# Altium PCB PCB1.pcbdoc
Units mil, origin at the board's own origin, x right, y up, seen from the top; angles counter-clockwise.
Board outline 2074.8 x 2271.65 mil, 2 copper layers (Top Layer, Bottom Layer); 7 components, 8 nets, 23 pads, 0 vias.
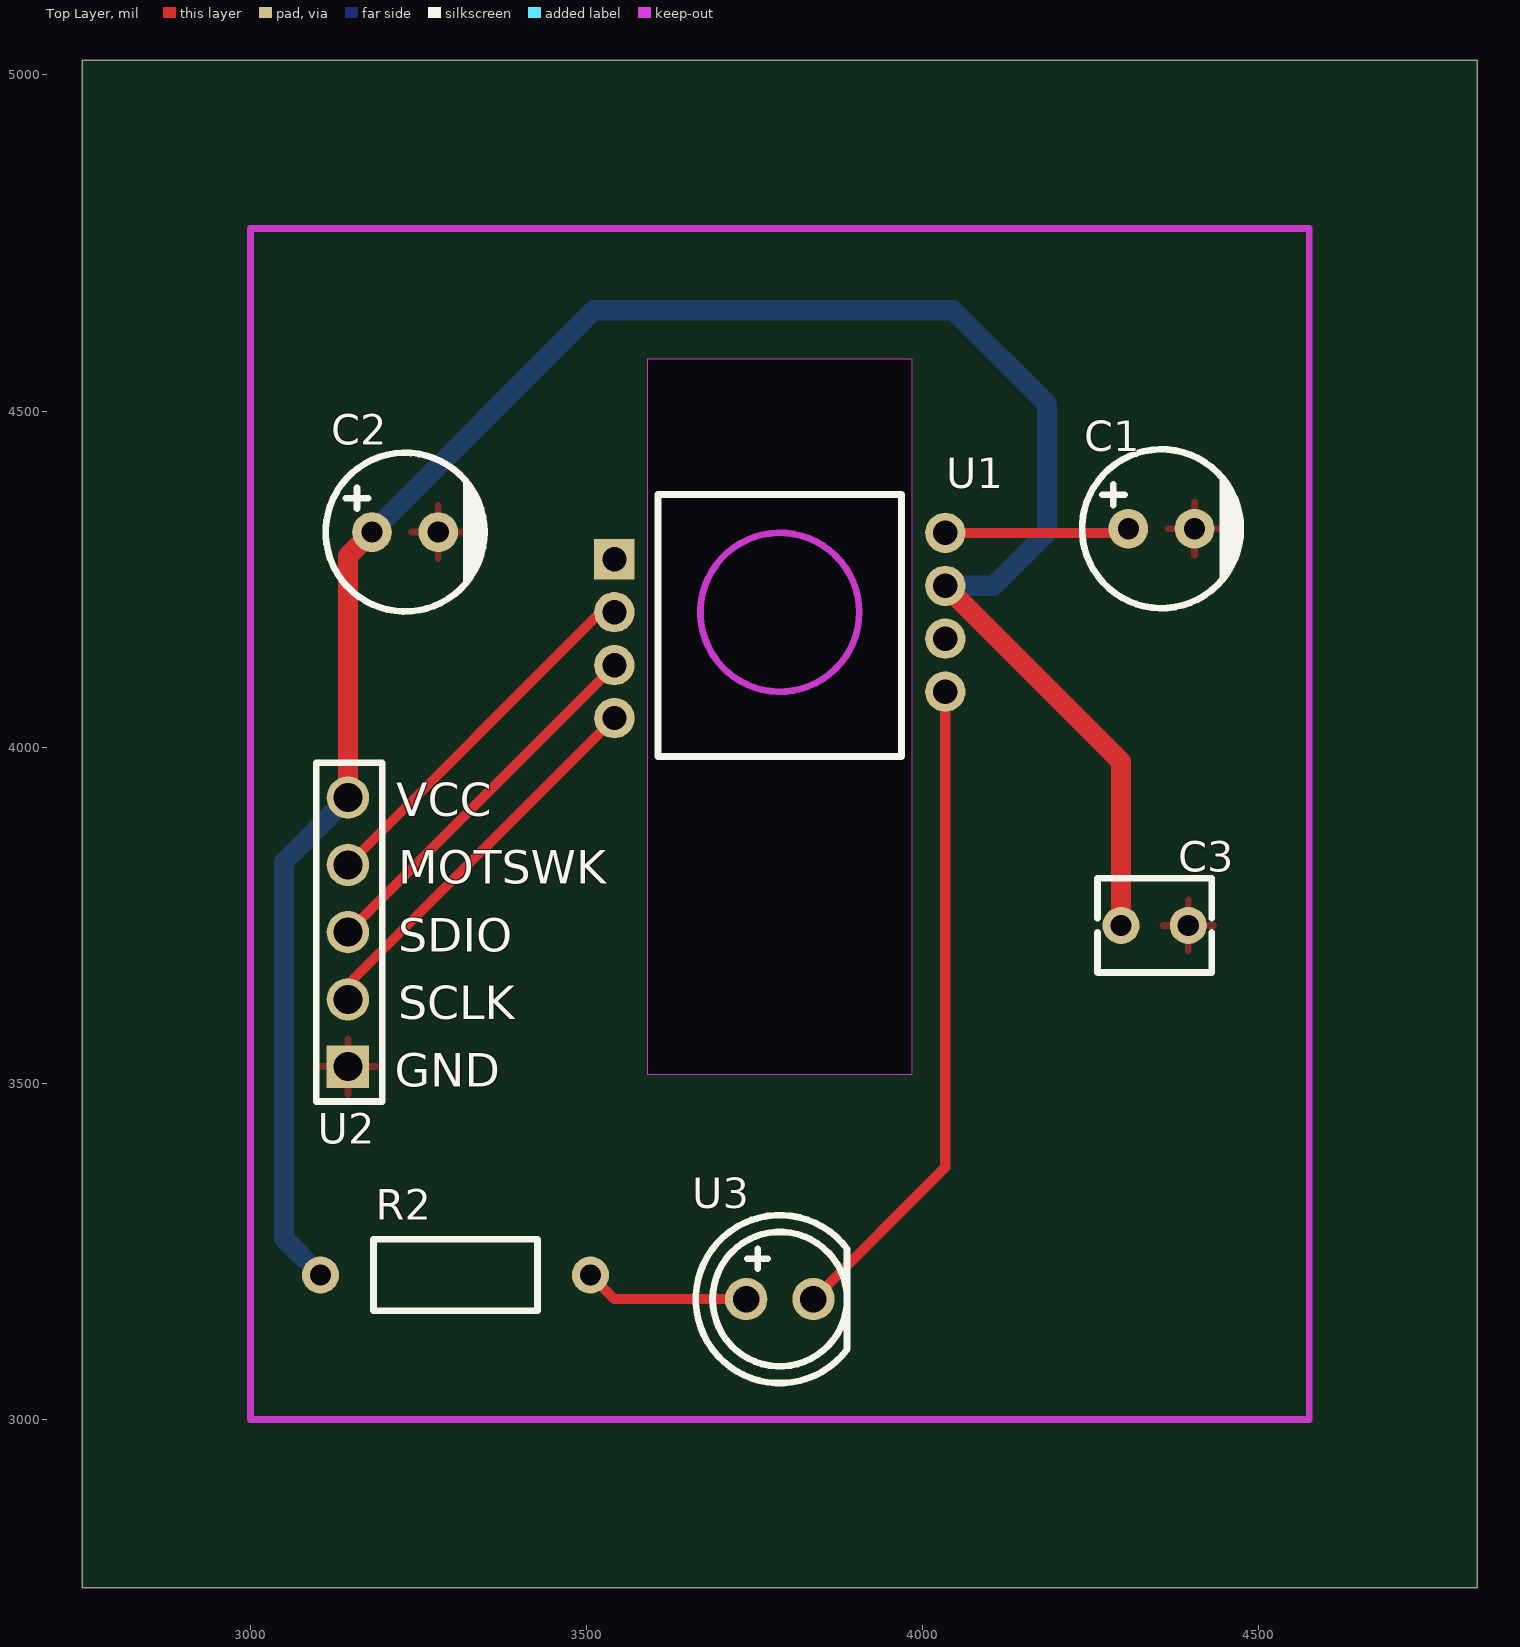
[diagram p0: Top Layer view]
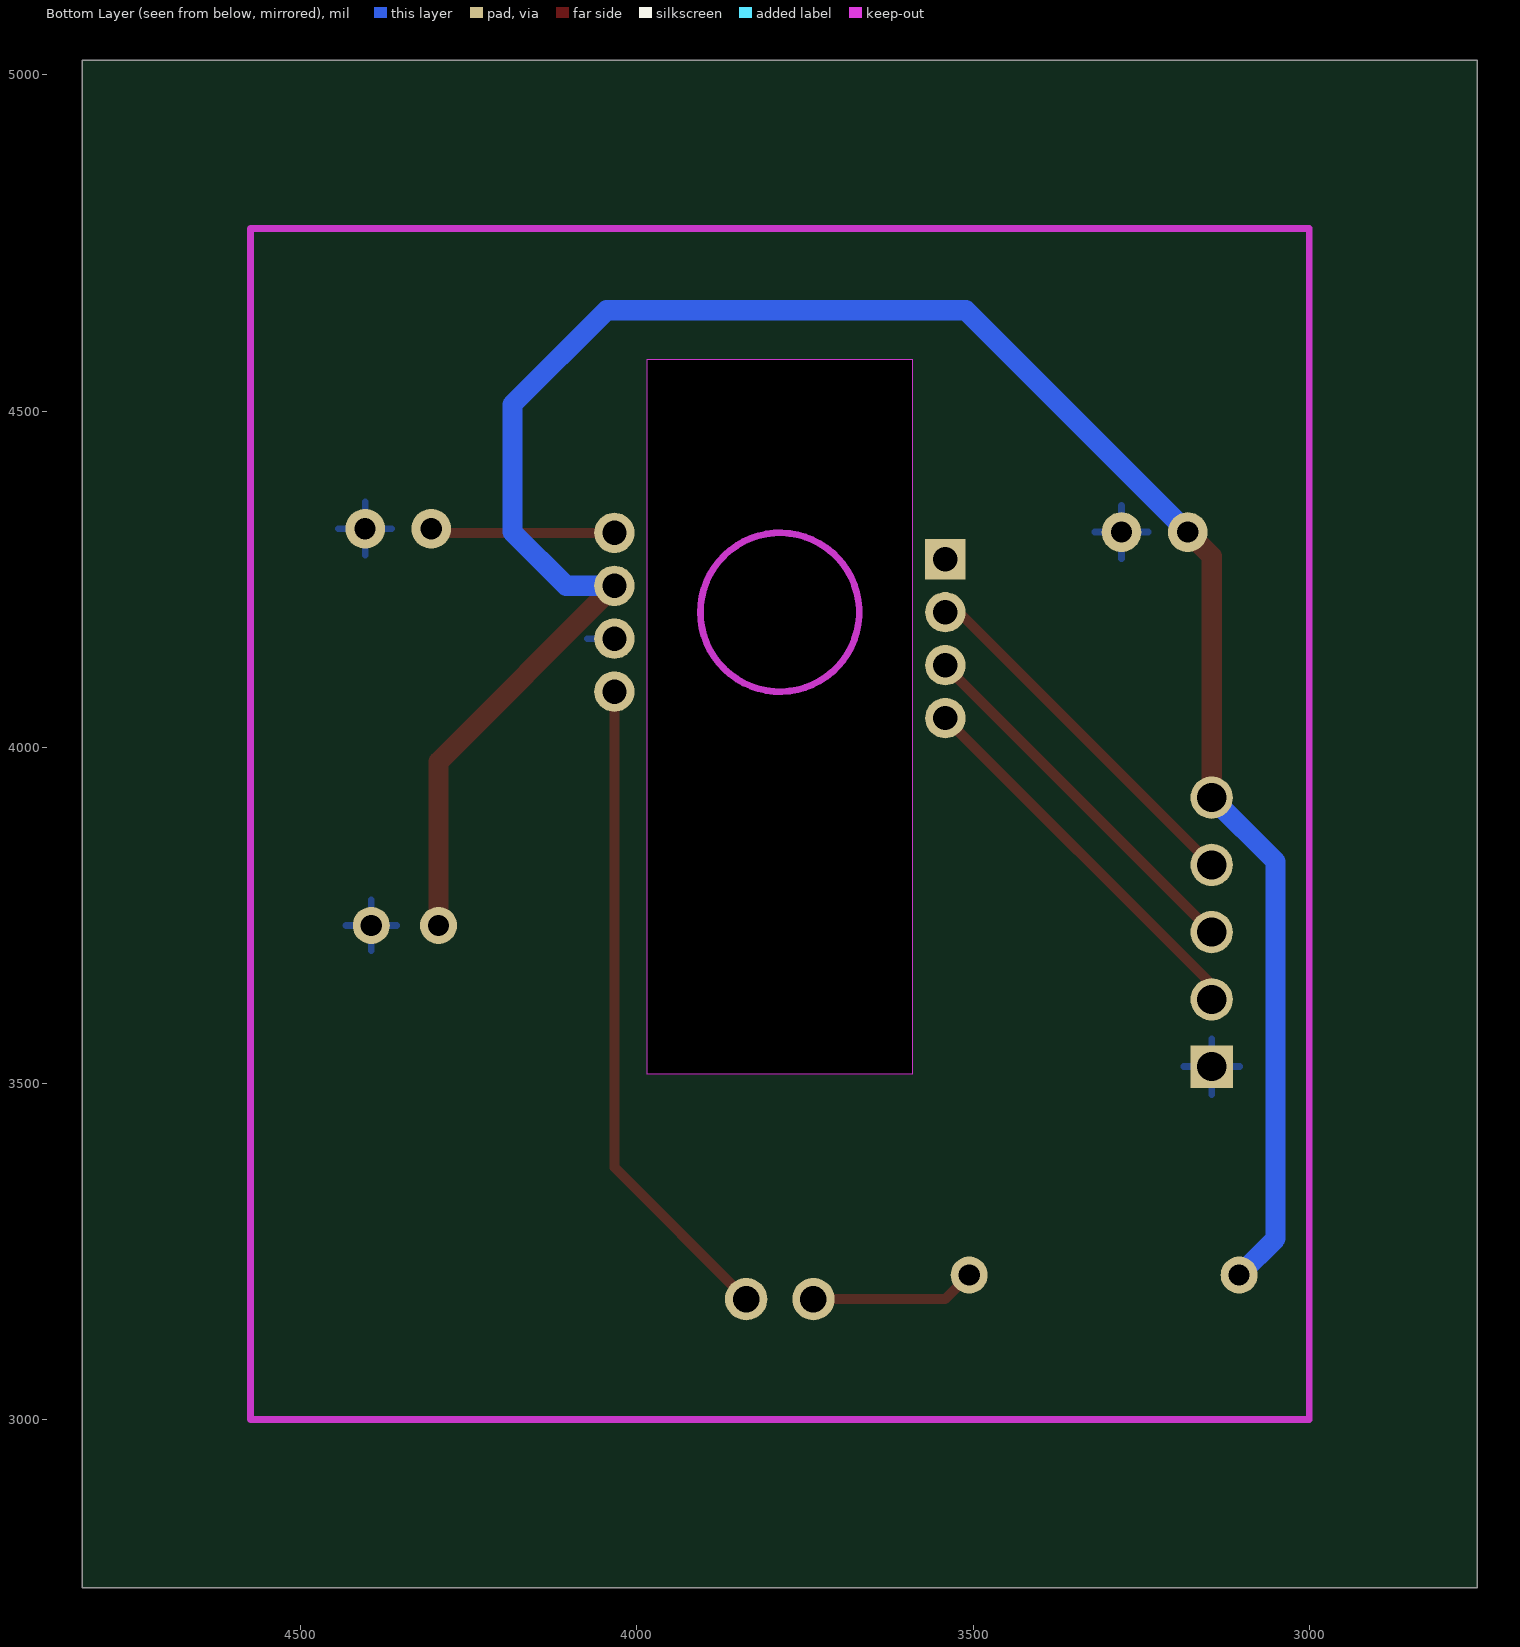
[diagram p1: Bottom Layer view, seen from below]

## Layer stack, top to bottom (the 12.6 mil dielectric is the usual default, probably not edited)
Top Layer: signal copper (thickness not stored)
Dielectric: dielectric 12.6, FR-4, Dk 4.8
Bottom Layer: signal copper (thickness not stored)

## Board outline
4824.8,2750 2750,2750 2750,5021.65 4824.8,5021.65
cut-out: 3590.55,3513.78 3984.25,3513.78 3984.25,4576.77 3590.55,4576.77

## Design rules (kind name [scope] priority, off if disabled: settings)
Clearance copperThickness1oz [All] p1: gap=7 ignorepadtopadclearanceinfootprint=FALSE except(4: Track-Track; 6: Track-SMDPad SMDPad-SMDPad Track-THPad SMDPad-THPad THPad-THPad Track-Via SMDPad-Via THPad-Via Via-Via SMDPad-Fill THPad-Fill Via-Fill Fill-Fill Track-Region SMDPad-Region THPad-Region Via-Region Region-Region Track-Poly SMDPad-Poly THPad-Poly Via-Poly Fill-Poly Region-Poly Poly-Poly Track-Text SMDPad-Text THPad-Text Via-Text Fill-Text Region-Text Poly-Text Text-Text; 6.9: Track-Hole SMDPad-Hole THPad-Hole Via-Hole Fill-Hole Region-Hole Poly-Hole Text-Hole Sheet-Hole; 11.8: Track-Fill Fill-Region Track-Sheet SMDPad-Sheet THPad-Sheet Via-Sheet Fill-Sheet Region-Sheet Poly-Sheet Text-Sheet)
Clearance copperThickness2oz [All] p1: gap=7 ignorepadtopadclearanceinfootprint=FALSE except(6: Track-SMDPad SMDPad-SMDPad Track-THPad SMDPad-THPad THPad-THPad Track-Via SMDPad-Via THPad-Via Via-Via SMDPad-Fill THPad-Fill Via-Fill Fill-Fill Track-Region SMDPad-Region THPad-Region Via-Region Region-Region Track-Poly SMDPad-Poly THPad-Poly Via-Poly Fill-Poly Region-Poly Poly-Poly Track-Text SMDPad-Text THPad-Text Via-Text Fill-Text Region-Text Poly-Text Text-Text; 6.9: Track-Hole SMDPad-Hole THPad-Hole Via-Hole Fill-Hole Region-Hole Poly-Hole Text-Hole Sheet-Hole; 8: Track-Track; 11.8: Track-Fill Fill-Region Track-Sheet SMDPad-Sheet THPad-Sheet Via-Sheet Fill-Sheet Region-Sheet Poly-Sheet Text-Sheet)
DiffPairsRouting differentialPair [All] p1: maxuncoupledlength=10 maxlimit=6 mostfreqgap=6 toplayer_minwidth=5 toplayer_prefwidth=10 toplayer_maxwidth=100 bottomlayer_minwidth=5 bottomlayer_prefwidth=10 bottomlayer_maxwidth=100
PasteMaskExpansion pasteMaskExpansion [All] p1:
PlaneConnect innerPlane [All] p1: planeconnectstyle=Relief reliefexpansion=20 reliefentries=4 reliefconductorwidth=10 reliefairgap=10
PolygonConnect copperRegion [All] p1: connectstyle=Relief reliefentries=4 reliefconductorwidth=10 polygonreliefangle="90 Angle" airgapwidth=10
RoutingVias viaSize [All] p1: viastyle="Through Hole" holewidth=12.0078 minholewidth=11.811 maxholewidth=248.0314 width=24.0158 minwidth=19.685 maxwidth=393.7008
SolderMaskExpansion solderMaskExpansion [All] p1: useseparateexpansions=TRUE expansion=2 expansionbottom=2
Width copperThickness1oz [All] p1: maxlimit=100 minlimit=5 preferedwidth=10
Width copperThickness2oz [All] p1: maxlimit=100 minlimit=8 preferedwidth=10

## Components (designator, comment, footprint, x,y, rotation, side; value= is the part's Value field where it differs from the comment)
C1 "CD110477M1A0607VFL" CAP-TH_BD6.0-P2.50-D0.5-FD 4355,4325 r0 top
C2 "CD110477M1A0607VFL" CAP-TH_BD6.0-P2.50-D0.5-FD 3230,4320 r0 top
C3 "178MU0006" CAP-TH_L4.2-W3.5-P2.54-D0.5 4345,3735 r180 top
R2 "MF1/4W-1K±1%-ST52" RES-TH_BD2.7-L6.2-P10.20-D0.4 3305,3215 r180 top
U1 "PAW3212DB-TJDT" SENSOR-TH_PAW3212DB-TJDT 3787.4,4181.1 r270 top locked
U2 "双塑单排排针5PIN2.54间距" HDR-TH_5P-P2.54-V-M-A 3145,3725 r90 top
U3 "MHL5013UGTC" LED-TH_BD5.0-P2.54-FD 3787.4,3179.13 r0 top locked

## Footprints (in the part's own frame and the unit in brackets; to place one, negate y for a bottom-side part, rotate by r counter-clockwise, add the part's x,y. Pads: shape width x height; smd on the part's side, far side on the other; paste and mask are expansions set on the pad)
CAP-TH_BD6.0-P2.50-D0.5-FD [mm]
  round 1.5 hole 0.8: 1(-1.25,0) 2(1.25,0)
  silkscreen extent -3,-3 3.08,3
CAP-TH_L4.2-W3.5-P2.54-D0.5 [mm]
  round 1.4 hole 0.8: 1(-1.27,0) 2(1.27,0)
  silkscreen extent -2.16,-1.78 2.16,1.78
HDR-TH_5P-P2.54-V-M-A [mm]
  rect 1.6x1.6 hole 1.1: 1(-5.08,0)
  round 1.6 hole 1.1: 2(-2.54,0) 3(0,0) 4(2.54,0) 5(5.08,0)
  silkscreen extent -6.4,-1.3 6.4,1.2
LED-TH_BD5.0-P2.54-FD [mm]
  round 1.6 hole 1: 1(-1.27,0) 2(1.27,0)
  silkscreen extent -3.17,-3.17 2.54,3.17
RES-TH_BD2.7-L6.2-P10.20-D0.4 [mm]
  round 1.4 hole 0.8 copper offset 0,0: 1(-5.1,0) 2(5.1,0)
  silkscreen extent -3.1,-1.35 3.1,1.35
SENSOR-TH_PAW3212DB-TJDT [mil]
  rect 60x60 hole 36: 1(-98.43,-246.06)
  round 60 hole 36: 2(-19.69,-246.06) 3(59.05,-246.06) 4(137.79,-246.06) 5(98.43,246.06) 6(19.69,246.06) 7(-59.05,246.06) 8(-137.79,246.06)
  Multi-Layer board cut-out: -19.69,118.11 -78.65,102.21 -121.79,58.99 -137.58,0 -121.79,-58.99 -78.65,-102.21 -19.69,-118.11 -19.69,-118.11 39.28,-102.22 82.42,-59 98.21,0 82.42,58.99 39.28,102.21 -19.68,118.11
  Multi-Layer keep-out circle w10: c-19.69,0 r118.11
  silkscreen extent -195,-181 195,181

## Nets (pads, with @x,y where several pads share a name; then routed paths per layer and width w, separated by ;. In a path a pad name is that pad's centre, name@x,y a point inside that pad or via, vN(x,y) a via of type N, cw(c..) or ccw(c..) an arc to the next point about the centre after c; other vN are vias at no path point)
$1N151: C1.1 U1.8 | length 274.9
  Top Layer w15: U1.8 4299.68,4318.9 C1.1
$1N588: U1.5 U3.2 | length 984.8
  Top Layer w15: U3.2 4033.46,3375.19 U1.5
$1N615: R2.1 U3.1 | length 246.5
  Top Layer w15: R2.1 3541.66,3179.13 U3.1
GND: C1.2 C2.2 C3.1 U1.6 U2.1
MOTSWK: U1.2 U2.4 | length 552
  Top Layer w15: U2.4 3520.79,4200.79 U1.2
SCLK: U1.4 U2.2 | length 582.5
  Top Layer w15: U2.2 3145,3646.97 U1.4
SDIO: U1.3 U2.3 | length 561.2
  Top Layer w15: U2.3 3541.34,4121.34 U1.3
VCC_DC: 
pads on no net: C2.1 C3.2 R2.2 U1.1 U1.7 U2.5
copper on no net: | length 3368.6
  Top Layer w30: 3145,3925 3145,4284.22 3180.78,4320 ; 4033.46,4240.16 4295,3978.62 4295,3735
  Bottom Layer w30: 3104.21,3215 3050,3269.21 3050,3830 3145,3925 ; 3180.78,4320 3510.78,4650 4045,4650 4185,4510 4185,4320 4105.16,4240.16 4033.46,4240.16

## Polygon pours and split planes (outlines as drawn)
GND on Top Layer (solid, remove dead copper): 3000,3000 4574.8,3000 4574.8,4771.65 3000,4771.65
GND on Bottom Layer (solid, remove dead copper, pour order 2): 3000,3000 4574.8,3000 4574.8,4771.65 3000,4771.65

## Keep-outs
Board Outline Layer:
  lines w10: 3000,3000 4574.8,3000 4574.8,4771.65 3000,4771.65 3000,3000
Multi-Layer:
  region: 3590.55,3513.78 3984.25,3513.78 3984.25,4576.77 3590.55,4576.77

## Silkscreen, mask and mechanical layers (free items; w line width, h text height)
Top Silkscreen Layer:
  text "VCC" at 3217.2,3897.2 h50
  text "MOTSWK" at 3220.01,3796.65 h50
  text "SDIO" at 3220,3696.1 h50
  text "SCLK" at 3220,3595.55 h50
  text "GND" at 3215,3495 h50
Mechanical Layer:
  lines w1: 3590.55,3513.78 3984.25,3513.78 3984.25,4576.77 3590.55,4576.77 3590.55,3513.78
